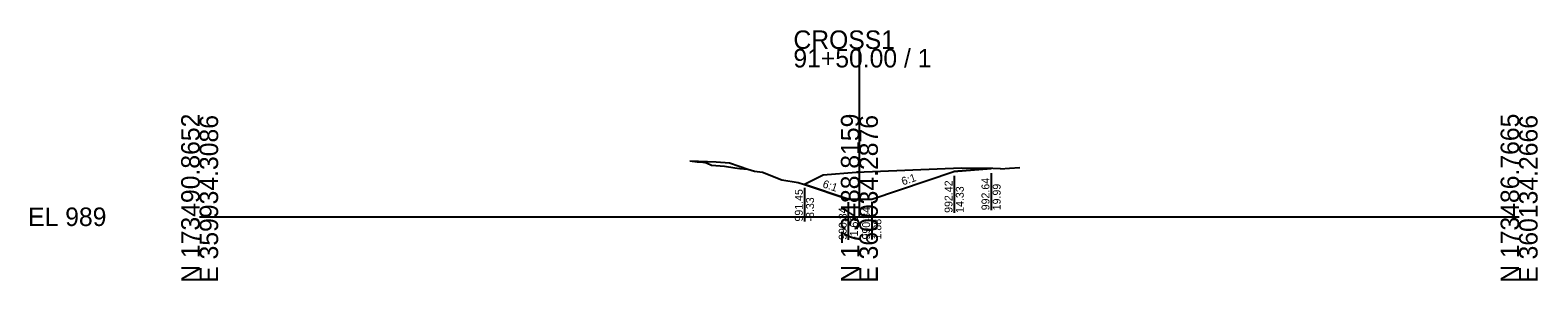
# Model space of a CAD drawing. Extents: x -26 to 1403, y -10 to 11027.
# Drawn here: x -25.7 to 202.8, y 6490.3 to 6528.2 of the extents above; entities that cross this region are included whole.
import ezdxf

# ---------------------------------------------------------------- set-up
doc = ezdxf.new("R2010")
doc.units = 0
for name, color, linetype in [('Default', 7, 'Continuous'), ('P_E_XS_Ground', 7, 'Continuous'), ('P_XS', 7, 'Continuous'), ('P_XS_EAR_CommonGrnd', 7, 'Continuous'), ('P_XS_Lane', 7, 'Continuous'), ('P_XS_Rock', 7, 'Continuous')]:
    doc.layers.add(name, color=color, linetype=linetype)

msp = doc.modelspace()

# ---------------------------------------------------------------- linework, layer by layer
at = {"layer": 'Default'}
for p, q in [((100, 6500), (100, 6525.4)), ((0, 6500), (100, 6500)), ((100, 6500), (200, 6500))]:
    msp.add_line(p, q, dxfattribs=at)
at = {"layer": 'P_E_XS_Ground'}
for p, q in [((74.32, 6508.47), (75.39, 6508.32)), ((75.39, 6508.32), (76.25, 6508.27)), ((76.25, 6508.27), (76.82, 6508.15)), ((76.82, 6508.15), (77.6, 6507.82)), ((77.6, 6507.82), (79.57, 6507.64)), ((79.57, 6507.64), (81.1, 6507.43)), ((81.1, 6507.43), (81.9, 6507.31)), ((81.9, 6507.31), (83.08, 6507.21)), ((83.08, 6507.21), (84.11, 6506.92)), ((84.11, 6506.92), (85.33, 6506.73)), ((85.33, 6506.73), (88.25, 6505.6)), ((99.5, 6506.71), (94.5, 6506.31)), ((115.5, 6507.35), (99.5, 6506.71)), ((120.24, 6507.28), (115.5, 6507.35)), ((121.39, 6507.26), (120.24, 6507.28)), ((121.39, 6507.26), (122.77, 6507.35)), ((122.77, 6507.35), (124.33, 6507.47)), ((88.25, 6505.6), (90.71, 6505.19)), ((90.71, 6505.19), (91.67, 6504.9)), ((94.5, 6506.31), (91.67, 6504.9))]:
    msp.add_line(p, q, dxfattribs=at)
at = {"layer": 'P_XS'}
for p, q in [((74.3, 6508.47), (78.3, 6508.31)), ((78.3, 6508.31), (80.3, 6508.15)), ((80.3, 6508.15), (83.24, 6507.16))]:
    msp.add_line(p, q, dxfattribs=at)
at = {"layer": 'P_XS_EAR_CommonGrnd'}
msp.add_lwpolyline([(98.32, 6502.68), (101.88, 6502.68), (114.33, 6506.83), (119.99, 6507.28), (115.5, 6507.35), (99.5, 6506.71), (94.5, 6506.31), (91.67, 6504.9)], close=True, dxfattribs=at)
at = {"layer": 'P_XS_Lane'}
for p, q in [((101.88, 6502.68), (114.33, 6506.83)), ((119.99, 6507.28), (114.33, 6506.83)), ((98.32, 6502.68), (91.67, 6504.9)), ((98.32, 6502.68), (101.88, 6502.68))]:
    msp.add_line(p, q, dxfattribs=at)
at = {"layer": 'P_XS_Rock'}
for p, q in [((119.96, 6506.6), (119.96, 6500.98)), ((91.67, 6504.4), (91.67, 6499.28)), ((114.37, 6506.2), (114.37, 6500.59)), ((98.32, 6502.21), (98.32, 6496.5)), ((101.87, 6502.27), (101.87, 6496.56))]:
    msp.add_line(p, q, dxfattribs=at)

# ---------------------------------------------------------------- texts
at = {"layer": 'Default'}
for s, p in [('CROSS1', (90, 6525.4)), ('91+50.00 / 1', (90, 6522.6)), ('EL 989', (-26, 6498.6))]:
    msp.add_text(s, height=2.8, dxfattribs=at).set_placement(p)
for s, p in [('N 173490.8652', (0, 6490)), ('E 359934.3086', (2.8, 6490)), ('N 173488.8159', (100, 6490)), ('E 360034.2876', (102.8, 6490)), ('N 173486.7665', (200, 6490)), ('E 360134.2666', (202.8, 6490))]:
    msp.add_text(s, height=2.8, rotation=90, dxfattribs=at).set_placement(p)
at = {"layer": 'P_XS_Rock'}
for s, rotation, p in [('6:1', 18.4349, (106.6, 6504.74)), ('991.45', 90, (91.42, 6499.28)), ('6:1', 341.5651, (94.33, 6504.48)), ('992.42', 90, (114.12, 6500.59)), ('14.33', 90, (115.82, 6500.59)), ('992.64', 90, (119.71, 6500.98)), ('19.99', 90, (121.41, 6500.98)), ('-8.33', 90, (93.12, 6499.28)), ('990.34', 90, (98.07, 6496.5)), ('-1.68', 90, (99.77, 6496.5)), ('990.34', 90, (101.62, 6496.56)), ('1.88', 90, (103.32, 6496.56))]:
    msp.add_text(s, height=1.2, rotation=rotation, dxfattribs=at).set_placement(p)

doc.saveas('drawing.dxf')
